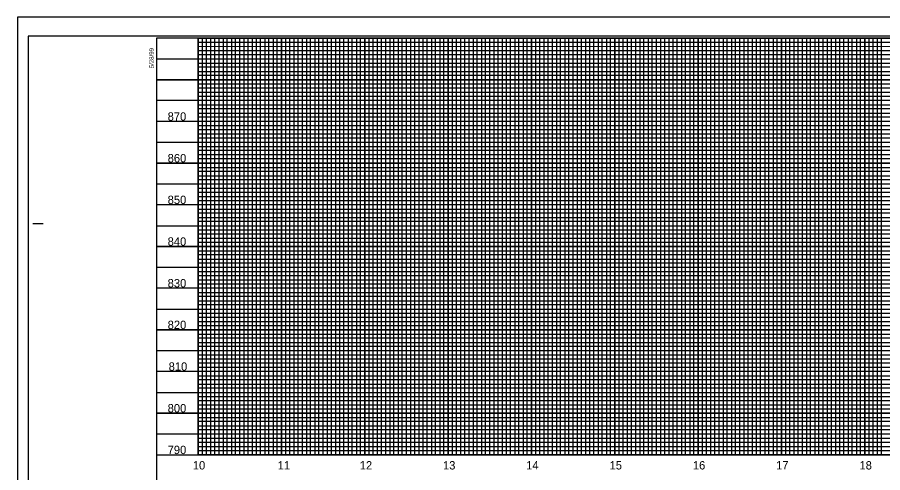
# Model space of a CAD drawing. Extents: x 1755181 to 1757273, y 729911 to 735411.
# Drawn here: x 1755181 to 1756219, y 734864 to 735411 of the extents above; entities that cross this region are included whole.
import ezdxf

# ---------------------------------------------------------------- set-up
doc = ezdxf.new("R2010")
doc.units = 0
for name, color, linetype in [('Exist Vertical Profile Horizontal Axis Label Major', 7, 'Continuous'), ('Exist Vertical Profile Vertical Axis Label', 7, 'Continuous'), ('Scratch_Level_3', 7, 'Continuous'), ('Sheet Cutting Line CELL', 7, 'Continuous'), ('Sheet DOT Grid CELL', 7, 'Continuous'), ('Sheet Plot Border Inside CELL', 7, 'Continuous'), ('Sheet Plot Border Outside CELL', 7, 'Continuous'), ('Sheet Profile CELL', 7, 'Continuous'), ('Sheet Profile Grid Major CELL', 7, 'Continuous'), ('Sheet Profile Grid Middle CELL', 7, 'Continuous'), ('Sheet Profile Grid Minor CELL', 7, 'Continuous')]:
    doc.layers.add(name, color=color, linetype=linetype)

msp = doc.modelspace()

# ---------------------------------------------------------------- linework, layer by layer
at = {"layer": 'Scratch_Level_3'}
msp.add_lwpolyline([(1755397.7, 734885.9), (1755397.7, 735385.8), (1756647.7, 735385.8), (1756647.6, 735152.8), (1756797.7, 735152.8), (1756797.7, 734885.9)], close=True, dxfattribs=at)
at = {"layer": 'Sheet Cutting Line CELL'}
for p, q in [((1756864.7, 735410.8), (1755180.7, 735410.8)), ((1755180.7, 735410.8), (1755180.7, 734310.8))]:
    msp.add_line(p, q, dxfattribs=at)
at = {"layer": 'Sheet DOT Grid CELL'}
for p, q in [((1755397.7, 734885.8), (1755397.7, 735385.8)), ((1755447.7, 734885.8), (1755447.7, 735385.8)), ((1755497.7, 734885.8), (1755497.7, 735385.8)), ((1755547.7, 734885.8), (1755547.7, 735385.8)), ((1755597.7, 734885.8), (1755597.7, 735385.8)), ((1755647.7, 734885.8), (1755647.7, 735385.8)), ((1755697.7, 734885.8), (1755697.7, 735385.8)), ((1755747.7, 734885.8), (1755747.7, 735385.8)), ((1755797.7, 734885.8), (1755797.7, 735385.8)), ((1755847.7, 734885.8), (1755847.7, 735385.8)), ((1755897.7, 734885.8), (1755897.7, 735385.8)), ((1755947.7, 734885.8), (1755947.7, 735385.8)), ((1755997.7, 734885.8), (1755997.7, 735385.8)), ((1756047.7, 734885.8), (1756047.7, 735385.8)), ((1756097.7, 734885.8), (1756097.7, 735385.8)), ((1756147.7, 734885.8), (1756147.7, 735385.8)), ((1756197.7, 734885.8), (1756197.7, 735385.8)), ((1756647.6, 735335.8), (1755347.7, 735335.8)), ((1756647.6, 735285.8), (1755347.7, 735285.8)), ((1756647.7, 735235.8), (1755347.7, 735235.8)), ((1756647.6, 735185.8), (1755347.7, 735185.8)), ((1756847.7, 735135.8), (1755347.7, 735135.8)), ((1756847.7, 735085.8), (1755347.7, 735085.8)), ((1756847.7, 735035.8), (1755347.7, 735035.8)), ((1756847.7, 734985.8), (1755347.7, 734985.8)), ((1756847.7, 734935.8), (1755347.7, 734935.8))]:
    msp.add_line(p, q, dxfattribs=at)
at = {"layer": 'Sheet Plot Border Inside CELL'}
msp.add_lwpolyline([(1755193.7, 734333.2), (1756860.2, 734333.2), (1756860.2, 735388.3), (1755193.7, 735388.3)], close=True, dxfattribs=at)
at = {"layer": 'Sheet Plot Border Outside CELL'}
msp.add_lwpolyline([(1755180.7, 734310.8), (1756864.7, 734310.8), (1756864.7, 735410.8), (1755180.7, 735410.8)], close=True, dxfattribs=at)
at = {"layer": 'Sheet Profile CELL'}
for p, q in [((1755199.2, 735163.3), (1755211.7, 735163.3)), ((1755347.7, 734885.8), (1756847.7, 734885.8))]:
    msp.add_line(p, q, dxfattribs=at)
msp.add_lwpolyline([(1756847.7, 735385.8), (1755347.7, 735385.8), (1755347.7, 734335.8), (1756847.7, 734335.8)], close=True, dxfattribs=at)
at = {"layer": 'Sheet Profile Grid Major CELL'}
for points in [[(1755397.7, 735385.8), (1755397.7, 734885.8), (1755447.7, 734885.8), (1755447.7, 735385.8), (1755497.7, 735385.8), (1755497.7, 734885.8), (1755547.7, 734885.8), (1755547.7, 735385.8), (1755597.7, 735385.8), (1755597.7, 734885.8), (1755647.7, 734885.8), (1755647.7, 735385.8), (1755697.7, 735385.8), (1755697.7, 734885.8), (1755747.7, 734885.8), (1755747.7, 735385.8), (1755797.7, 735385.8), (1755797.7, 734885.8), (1755847.7, 734885.8), (1755847.7, 735385.8), (1755897.7, 735385.8), (1755897.7, 734885.8), (1755947.7, 734885.8), (1755947.7, 735385.8), (1755997.7, 735385.8), (1755997.7, 734885.8), (1756047.7, 734885.8), (1756047.7, 735385.8), (1756097.7, 735385.8), (1756097.7, 734885.8), (1756147.7, 734885.8), (1756147.7, 735385.8), (1756197.7, 735385.8), (1756197.7, 734885.8), (1756247.7, 734885.8)], [(1755347.7, 735335.8), (1756647.7, 735335.8)], [(1756647.7, 735285.8), (1755347.7, 735285.8), (1755347.7, 735235.8), (1756647.7, 735235.8)], [(1756647.6, 735185.8), (1755347.7, 735185.8), (1755347.7, 735135.8), (1756847.7, 735135.8)], [(1756847.7, 735085.8), (1755347.7, 735085.8), (1755347.7, 735035.8), (1756847.7, 735035.8)], [(1756847.7, 734985.8), (1755347.7, 734985.8), (1755347.7, 734985.8), (1755347.7, 734935.8), (1756847.7, 734935.8)]]:
    msp.add_lwpolyline(points, dxfattribs=at)
at = {"layer": 'Sheet Profile Grid Middle CELL'}
msp.add_line((1755347.7, 735360.8), (1756647.6, 735360.8), dxfattribs=at)
for points in [[(1755422.7, 735385.8), (1755422.7, 734885.8), (1755472.7, 734885.8), (1755472.7, 735385.8), (1755522.7, 735385.8), (1755522.7, 734885.8), (1755572.7, 734885.8), (1755572.7, 735385.8), (1755622.7, 735385.8), (1755622.7, 734885.8), (1755672.7, 734885.8), (1755672.7, 735385.8), (1755722.7, 735385.8), (1755722.7, 734885.8), (1755772.7, 734885.8), (1755772.7, 735385.8), (1755822.7, 735385.8), (1755822.7, 734885.8), (1755872.7, 734885.8), (1755872.7, 735385.8), (1755922.7, 735385.8), (1755922.7, 734885.8), (1755972.7, 734885.8), (1755972.7, 734885.8), (1755972.7, 735385.8), (1756022.7, 735385.8), (1756022.7, 734885.8), (1756072.7, 734885.8), (1756072.7, 735385.8), (1756122.7, 735385.8), (1756122.7, 734885.8), (1756172.7, 734885.8), (1756172.7, 735385.8), (1756222.7, 735385.8)], [(1756647.7, 735310.8), (1755347.7, 735310.8), (1755347.7, 735260.8), (1756647.7, 735260.8)], [(1756647.6, 735210.8), (1755347.7, 735210.8), (1755347.7, 735160.8), (1756647.6, 735160.8)], [(1756847.7, 735110.8), (1755347.7, 735110.8), (1755347.7, 735060.8), (1756847.7, 735060.8)], [(1756847.7, 735010.8), (1755347.7, 735010.8), (1755347.7, 734960.8), (1756847.7, 734960.8)], [(1756847.7, 734910.8), (1755347.7, 734910.8)]]:
    msp.add_lwpolyline(points, dxfattribs=at)
at = {"layer": 'Sheet Profile Grid Minor CELL'}
for p, q in [((1755397.7, 735380.8), (1756647.7, 735380.8)), ((1755397.7, 735375.8), (1755397.7, 735375.8)), ((1756647.7, 735375.8), (1755397.7, 735375.4)), ((1755397.7, 735370.8), (1756647.7, 735370.8)), ((1756647.6, 735250.8), (1755397.7, 735250.8)), ((1756647.7, 735245.8), (1755397.7, 735245.8)), ((1756647.7, 735240.8), (1755397.7, 735240.8)), ((1755397.7, 735230.8), (1756647.7, 735230.8)), ((1756647.7, 735225.8), (1755397.7, 735225.8)), ((1755397.7, 735220.8), (1756647.6, 735220.8)), ((1756647.6, 735200.8), (1755397.7, 735200.8)), ((1755397.7, 735195.8), (1756647.6, 735195.8)), ((1756647.6, 735175.8), (1755397.7, 735175.8)), ((1755397.7, 735170.8), (1756647.6, 735170.8)), ((1756797.7, 735150.8), (1755397.7, 735150.8)), ((1755397.7, 735145.8), (1756797.7, 735145.8)), ((1756797.7, 735140.8), (1755397.7, 735140.8)), ((1755397.7, 735130.8), (1756797.7, 735130.8)), ((1756797.7, 735125.8), (1755397.7, 735125.8)), ((1755397.7, 735120.8), (1756797.7, 735120.8)), ((1756797.7, 735115.8), (1755397.7, 735115.8)), ((1755397.7, 735105.8), (1756797.7, 735105.8)), ((1756797.7, 735100.8), (1755397.7, 735100.8)), ((1755397.7, 735095.8), (1756797.7, 735095.8)), ((1756797.7, 735090.8), (1755397.7, 735090.8)), ((1755397.7, 735080.8), (1756797.7, 735080.8)), ((1756797.7, 735075.8), (1755397.7, 735075.8)), ((1755397.7, 735070.8), (1756797.7, 735070.8)), ((1756797.7, 735065.8), (1755397.7, 735065.8)), ((1755397.7, 735055.8), (1756797.7, 735055.8)), ((1756797.7, 735050.8), (1755397.7, 735050.8)), ((1755397.7, 735045.8), (1756797.7, 735045.8)), ((1756797.7, 735040.8), (1755397.7, 735040.8)), ((1755397.7, 735030.8), (1756797.7, 735030.8)), ((1756797.7, 735025.8), (1755397.7, 735025.8)), ((1755397.7, 735020.8), (1756797.7, 735020.8)), ((1756797.7, 735015.8), (1755397.7, 735015.8)), ((1755397.7, 735005.8), (1756797.7, 735005.8)), ((1756797.7, 735000.8), (1755397.7, 735000.8)), ((1756797.7, 734995.8), (1755397.7, 734995.8)), ((1756797.7, 734990.8), (1755397.7, 734990.8)), ((1755397.7, 734980.8), (1756797.7, 734980.8)), ((1756797.7, 734975.8), (1755397.7, 734975.8)), ((1755397.7, 734970.8), (1756797.7, 734970.8)), ((1756797.7, 734965.8), (1755397.7, 734965.8)), ((1755397.7, 734955.8), (1756797.7, 734955.8)), ((1756797.7, 734950.8), (1755397.7, 734950.8)), ((1755397.7, 734945.8), (1756797.7, 734945.8)), ((1756797.7, 734940.8), (1755397.7, 734940.8)), ((1755397.7, 734930.8), (1756797.7, 734930.8)), ((1756797.7, 734925.8), (1755397.7, 734925.8)), ((1755397.7, 734920.8), (1756797.7, 734920.8)), ((1756797.7, 734915.8), (1755397.7, 734915.8)), ((1755397.7, 734905.8), (1756797.7, 734905.8)), ((1756797.7, 734900.8), (1755397.7, 734900.8)), ((1755397.7, 734895.8), (1756797.7, 734895.8))]:
    msp.add_line(p, q, dxfattribs=at)
for points in [[(1755402.7, 735385.8), (1755402.7, 734885.8), (1755407.7, 734885.8), (1755407.7, 735385.8), (1755412.7, 735385.8), (1755412.7, 734885.8), (1755417.7, 734885.8), (1755417.7, 735385.8), (1755427.7, 735385.8), (1755427.7, 734885.8), (1755432.7, 734885.8), (1755432.7, 735385.8), (1755437.7, 735385.8), (1755437.7, 734885.8), (1755442.7, 734885.8), (1755452.7, 734885.8), (1755457.7, 734885.8), (1755457.7, 735385.8), (1755462.7, 735385.8), (1755462.7, 734885.8), (1755467.7, 734885.8), (1755467.7, 735385.8), (1755477.7, 735385.8), (1755477.7, 734885.8), (1755482.7, 734885.8), (1755482.7, 735385.8), (1755487.7, 735385.8), (1755487.7, 734885.8), (1755492.7, 734885.8), (1755492.7, 735385.8), (1755502.7, 735385.8), (1755502.7, 734885.8), (1755507.7, 734885.8), (1755507.7, 735385.8), (1755512.7, 735385.8), (1755512.7, 734885.8), (1755517.7, 734885.8), (1755517.7, 735385.8), (1755527.7, 735385.8), (1755527.7, 734885.8), (1755532.7, 734885.8), (1755532.7, 735385.8), (1755537.7, 735385.8), (1755537.7, 734885.8), (1755542.7, 734885.8), (1755542.7, 735385.8), (1755552.7, 735385.8), (1755552.7, 734885.8), (1755557.7, 734885.8), (1755557.7, 735385.8), (1755562.7, 735385.8), (1755562.7, 734885.8), (1755567.7, 734885.8), (1755567.7, 735385.8), (1755577.7, 735385.8), (1755577.7, 734885.8), (1755582.7, 734885.8), (1755582.7, 735385.8), (1755587.7, 735385.8), (1755587.7, 734885.8), (1755592.7, 734885.8), (1755592.7, 735385.8), (1755602.7, 735385.8), (1755602.7, 734885.8), (1755607.7, 734885.8), (1755607.7, 735385.8), (1755612.7, 735385.8), (1755612.7, 734885.8)], [(1755442.7, 734885.8), (1755442.7, 735385.8), (1755452.7, 735385.8), (1755452.7, 734885.8)], [(1755612.7, 734885.8), (1755617.7, 734885.8), (1755617.7, 735385.8), (1755627.7, 735385.8), (1755627.7, 734885.8), (1755632.7, 734885.8), (1755632.7, 735385.8), (1755637.7, 735385.8), (1755637.7, 734885.8), (1755642.7, 734885.8), (1755642.7, 735385.8), (1755652.7, 735385.8), (1755652.7, 734885.8), (1755657.7, 734885.8), (1755657.7, 735385.8), (1755662.7, 735385.8), (1755662.7, 734885.8), (1755667.7, 734885.8), (1755667.7, 735385.8), (1755677.7, 735385.8), (1755677.7, 734885.8), (1755682.7, 734885.8), (1755682.7, 735385.8), (1755687.7, 735385.8), (1755687.7, 734885.8), (1755692.7, 734885.8), (1755692.7, 735385.8), (1755702.7, 735385.8), (1755702.7, 734885.8), (1755707.7, 734885.8), (1755707.7, 735385.8), (1755712.7, 735385.8), (1755712.7, 734885.8), (1755717.7, 734885.8), (1755717.7, 735385.8), (1755727.7, 735385.8), (1755727.7, 734885.8), (1755732.7, 734885.8), (1755732.7, 735385.8), (1755737.7, 735385.8), (1755737.7, 734885.8), (1755742.7, 734885.8), (1755742.7, 735385.8), (1755752.7, 735385.8), (1755752.7, 734885.8), (1755757.7, 734885.8), (1755757.7, 735385.8), (1755762.7, 735385.8), (1755762.7, 734885.8), (1755767.7, 734885.8), (1755767.7, 735385.8), (1755777.7, 735385.8), (1755777.7, 734885.8), (1755782.7, 734885.8), (1755782.7, 735385.8), (1755787.7, 735385.8), (1755787.7, 734885.8), (1755792.7, 734885.8), (1755792.7, 735385.8), (1755802.7, 735385.8), (1755802.7, 734885.8), (1755807.7, 734885.8), (1755807.7, 735385.8), (1755812.7, 735385.8), (1755812.7, 734885.8), (1755817.7, 734885.8), (1755817.7, 735385.8), (1755827.7, 735385.8), (1755827.7, 734885.8), (1755832.7, 734885.8), (1755832.7, 735385.8), (1755837.7, 735385.8), (1755837.7, 734885.8), (1755842.7, 734885.8), (1755842.7, 735385.8), (1755852.7, 735385.8), (1755852.7, 734885.8), (1755857.7, 734885.8), (1755857.7, 735385.8), (1755862.7, 735385.8), (1755862.7, 734885.8), (1755867.7, 734885.8), (1755867.7, 735385.8), (1755877.7, 735385.8), (1755877.7, 734885.8), (1755882.7, 734885.8), (1755882.7, 735385.8), (1755887.7, 735385.8), (1755887.7, 734885.8), (1755892.7, 734885.8), (1755892.7, 735385.8), (1755902.7, 735385.8), (1755902.7, 734885.8), (1755907.7, 734885.8), (1755907.7, 735385.8), (1755912.7, 735385.8), (1755912.7, 734885.8), (1755917.7, 734885.8), (1755917.7, 735385.8), (1755927.7, 735385.8)], [(1755927.7, 735385.8), (1755927.7, 734885.8), (1755932.7, 734885.8), (1755932.7, 735385.8), (1755937.7, 735385.8), (1755937.7, 734885.8), (1755942.7, 734885.8), (1755942.7, 735385.8), (1755952.7, 735385.8), (1755952.7, 734885.8), (1755957.7, 734885.8), (1755957.7, 735385.8), (1755962.7, 735385.8), (1755962.7, 734885.8), (1755967.7, 734885.8), (1755967.7, 735385.8), (1755977.7, 735385.8), (1755977.7, 734885.8), (1755982.7, 734885.8), (1755982.7, 735385.8), (1755987.7, 735385.8), (1755987.7, 734885.8), (1755992.7, 734885.8), (1755992.7, 735385.8), (1756002.7, 735385.8), (1756002.7, 734885.8), (1756007.7, 734885.8), (1756007.7, 735385.8), (1756012.7, 735385.8), (1756012.7, 734885.8), (1756017.7, 734885.8), (1756017.7, 735385.8), (1756027.7, 735385.8), (1756027.7, 734885.8), (1756032.7, 734885.8), (1756032.7, 735385.8), (1756037.7, 735385.8), (1756037.7, 734885.8), (1756042.7, 734885.8), (1756042.7, 735385.8), (1756052.7, 735385.8), (1756052.7, 734885.8), (1756052.7, 734885.8), (1756057.7, 734885.8), (1756057.7, 735385.8), (1756062.7, 735385.8), (1756062.7, 734885.8), (1756067.7, 734885.8), (1756067.7, 735385.8), (1756077.7, 735385.8), (1756077.7, 734885.8), (1756082.7, 734885.8), (1756082.7, 735385.8), (1756087.7, 735385.8), (1756087.7, 734885.8), (1756092.7, 734885.8), (1756092.7, 735385.8), (1756102.7, 735385.8), (1756102.7, 734885.8), (1756107.7, 734885.8), (1756107.7, 735385.8), (1756112.7, 735385.8), (1756112.7, 734885.8), (1756117.7, 734885.8), (1756117.7, 735385.8), (1756127.7, 735385.8), (1756127.7, 734885.8), (1756132.7, 734885.8), (1756132.7, 735385.8), (1756137.7, 735385.8), (1756137.7, 734885.8), (1756142.7, 734885.8), (1756142.7, 735385.8), (1756152.7, 735385.8), (1756152.7, 734885.8), (1756157.7, 734885.8), (1756157.7, 735385.8), (1756162.7, 735385.8), (1756162.7, 734885.8), (1756167.7, 734885.8), (1756167.7, 735385.8), (1756177.7, 735385.8), (1756177.7, 734885.8), (1756182.7, 734885.8), (1756182.7, 735385.8), (1756187.7, 735385.8), (1756187.7, 734885.8), (1756192.7, 734885.8), (1756192.7, 735385.8), (1756202.7, 735385.8), (1756202.7, 734885.8), (1756207.4, 734886.3), (1756207.7, 734885.8), (1756207.7, 735385.8), (1756212.7, 735385.8), (1756212.7, 734885.8), (1756217.7, 734885.8), (1756217.7, 735385.8), (1756227.7, 735385.8)], [(1756647.7, 735365.8), (1755397.7, 735365.8), (1755397.7, 735355.8), (1756647.7, 735355.8)], [(1756647.6, 735350.8), (1755397.7, 735350.8), (1755397.7, 735345.8), (1756647.7, 735345.8)], [(1756647.7, 735340.8), (1755397.7, 735340.8), (1755397.7, 735330.8), (1756647.7, 735330.8)], [(1756647.7, 735325.8), (1755397.7, 735325.8), (1755397.7, 735320.8), (1756647.7, 735320.8)], [(1756647.7, 735315.8), (1755397.7, 735315.8), (1755397.7, 735305.8), (1756647.7, 735305.8)], [(1756647.7, 735300.8), (1755397.7, 735300.8), (1755397.7, 735295.8), (1756647.7, 735295.8)], [(1756647.7, 735290.8), (1755397.7, 735290.8), (1755397.7, 735280.8), (1756647.7, 735280.8)], [(1756647.7, 735275.7), (1755397.8, 735275.7), (1755397.8, 735270.8), (1756647.7, 735270.8)], [(1756647.7, 735265.8), (1755397.7, 735265.8), (1755397.7, 735255.8), (1756647.7, 735255.8)], [(1756647.6, 735215.8), (1755397.7, 735215.8), (1755397.7, 735205.8), (1756647.6, 735205.8)], [(1756647.6, 735190.8), (1755397.7, 735190.8), (1755397.7, 735180.8), (1756647.6, 735180.8)], [(1756647.6, 735165.8), (1755397.7, 735165.8), (1755397.7, 735155.8), (1756647.6, 735155.8)], [(1756797.7, 734890.8), (1755397.7, 734890.8)]]:
    msp.add_lwpolyline(points, dxfattribs=at)

# ---------------------------------------------------------------- texts
at = {"layer": 'Exist Vertical Profile Horizontal Axis Label Major'}
for s, p in [('10', (1755391.3, 734868.3)), ('11', (1755493.1, 734868.3)), ('12', (1755591.6, 734868.3)), ('13', (1755691.5, 734868.3)), ('14', (1755791.3, 734868.3)), ('15', (1755891.4, 734868.3)), ('16', (1755991.4, 734868.3)), ('17', (1756091.2, 734868.3)), ('18', (1756191.3, 734868.3))]:
    msp.add_text(s, height=10, dxfattribs=at).set_placement(p)
at = {"layer": 'Exist Vertical Profile Vertical Axis Label'}
for s, p in [('870', (1755361.1, 735286.8)), ('860', (1755361.1, 735236.8)), ('850', (1755361.1, 735186.8)), ('840', (1755361.1, 735136.8)), ('830', (1755361.1, 735086.8)), ('820', (1755361.1, 735036.8)), ('810', (1755362.3, 734986.8)), ('800', (1755361.1, 734936.8)), ('790', (1755361.1, 734886.8))]:
    msp.add_text(s, height=10, dxfattribs=at).set_placement(p)
at = {"layer": 'Sheet Profile CELL'}
msp.add_text('5/28/99', height=5.25, rotation=90, dxfattribs=at).set_placement((1755344.4, 735349.7))

doc.saveas('drawing.dxf')
